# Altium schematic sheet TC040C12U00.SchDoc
size A2
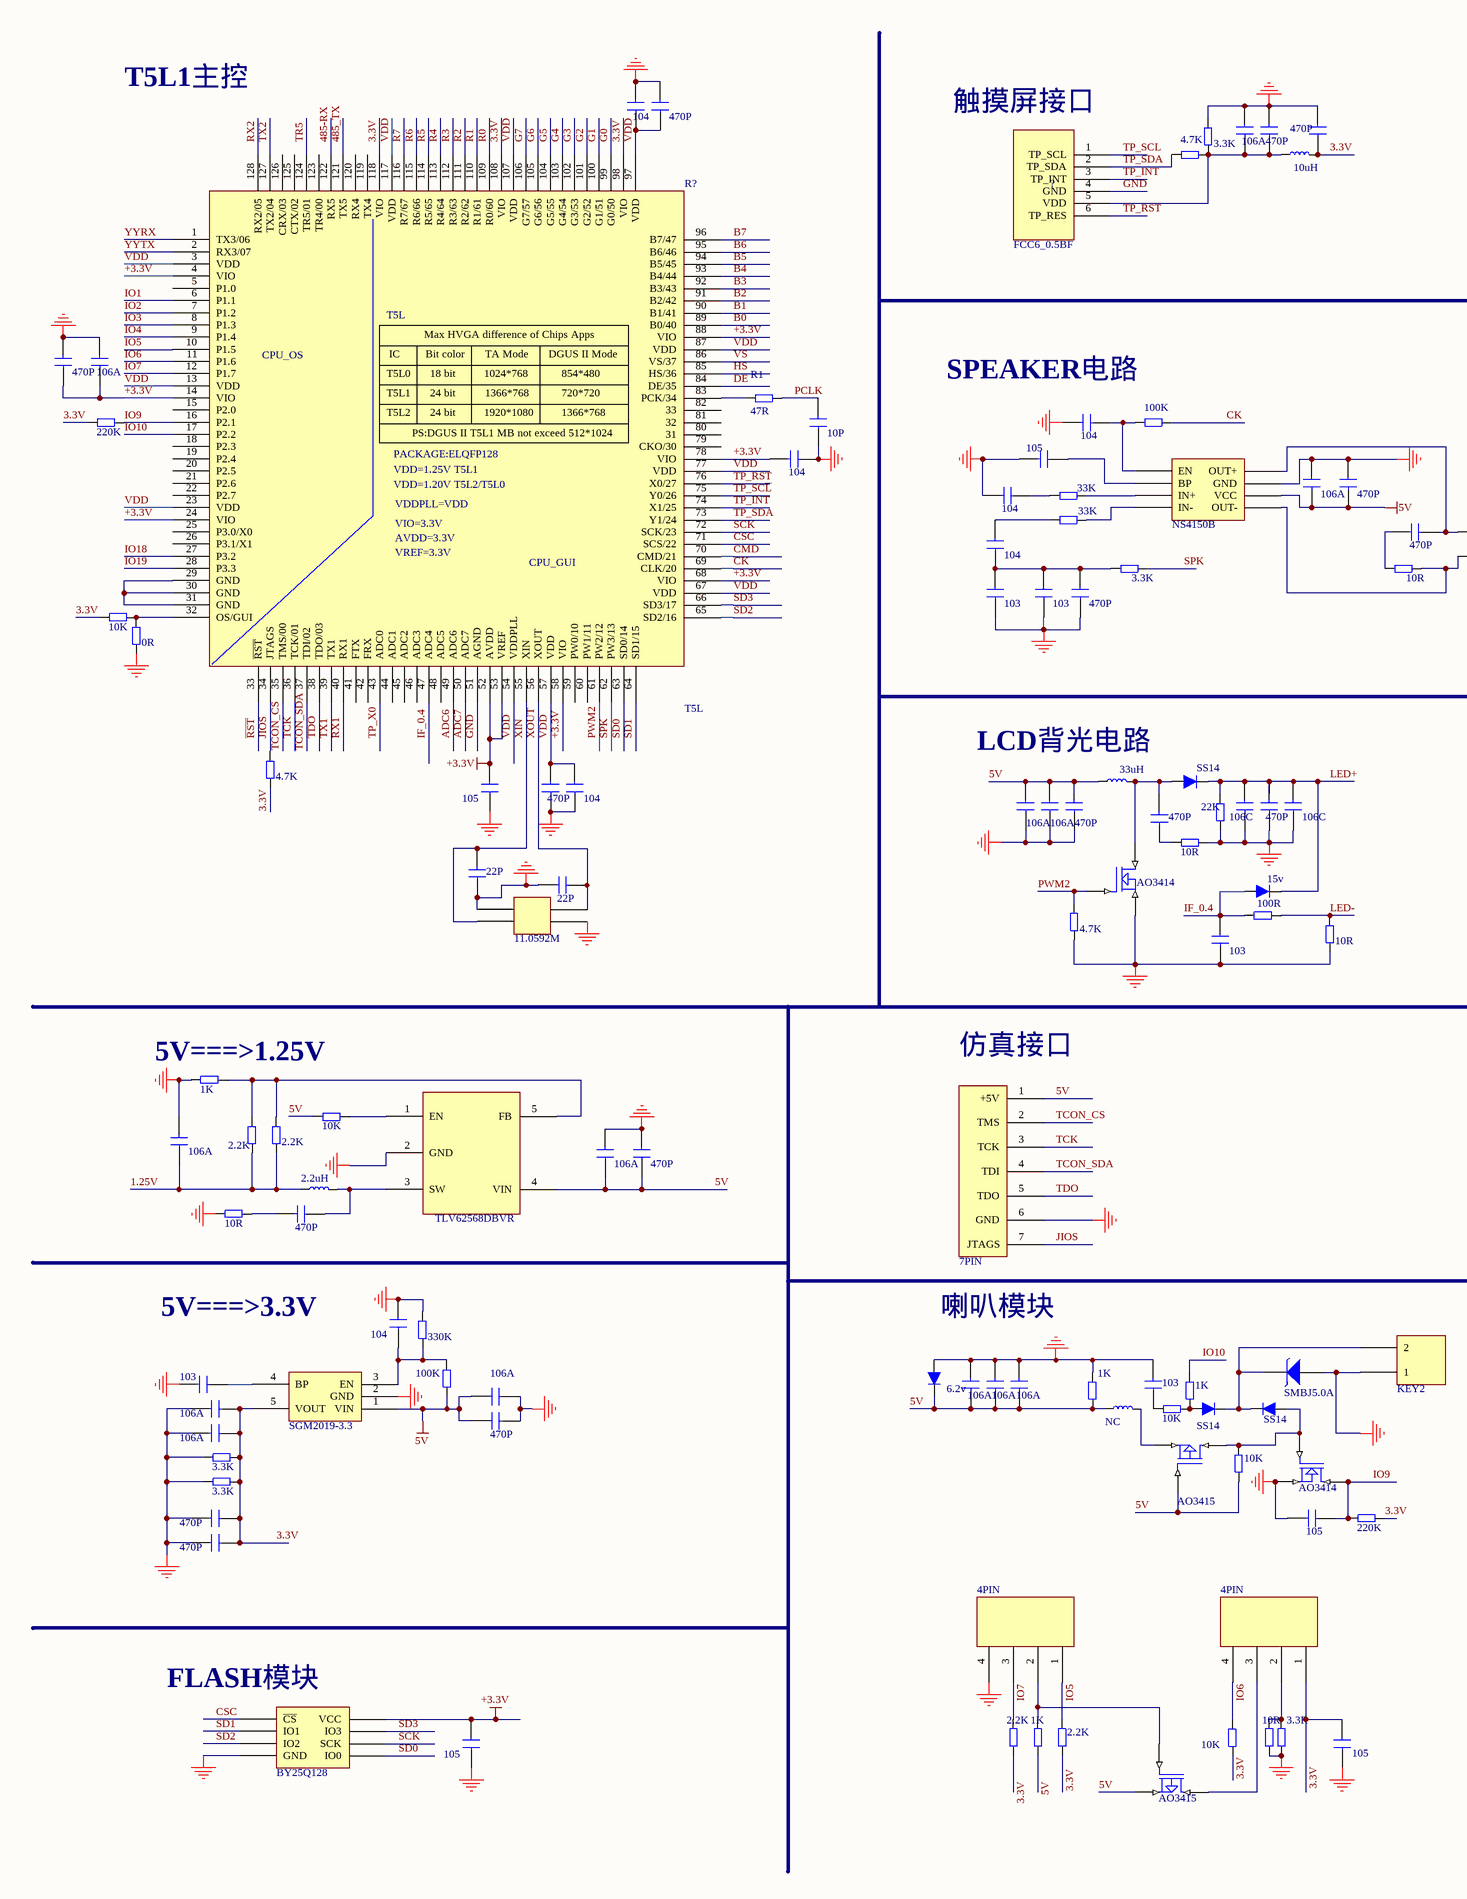
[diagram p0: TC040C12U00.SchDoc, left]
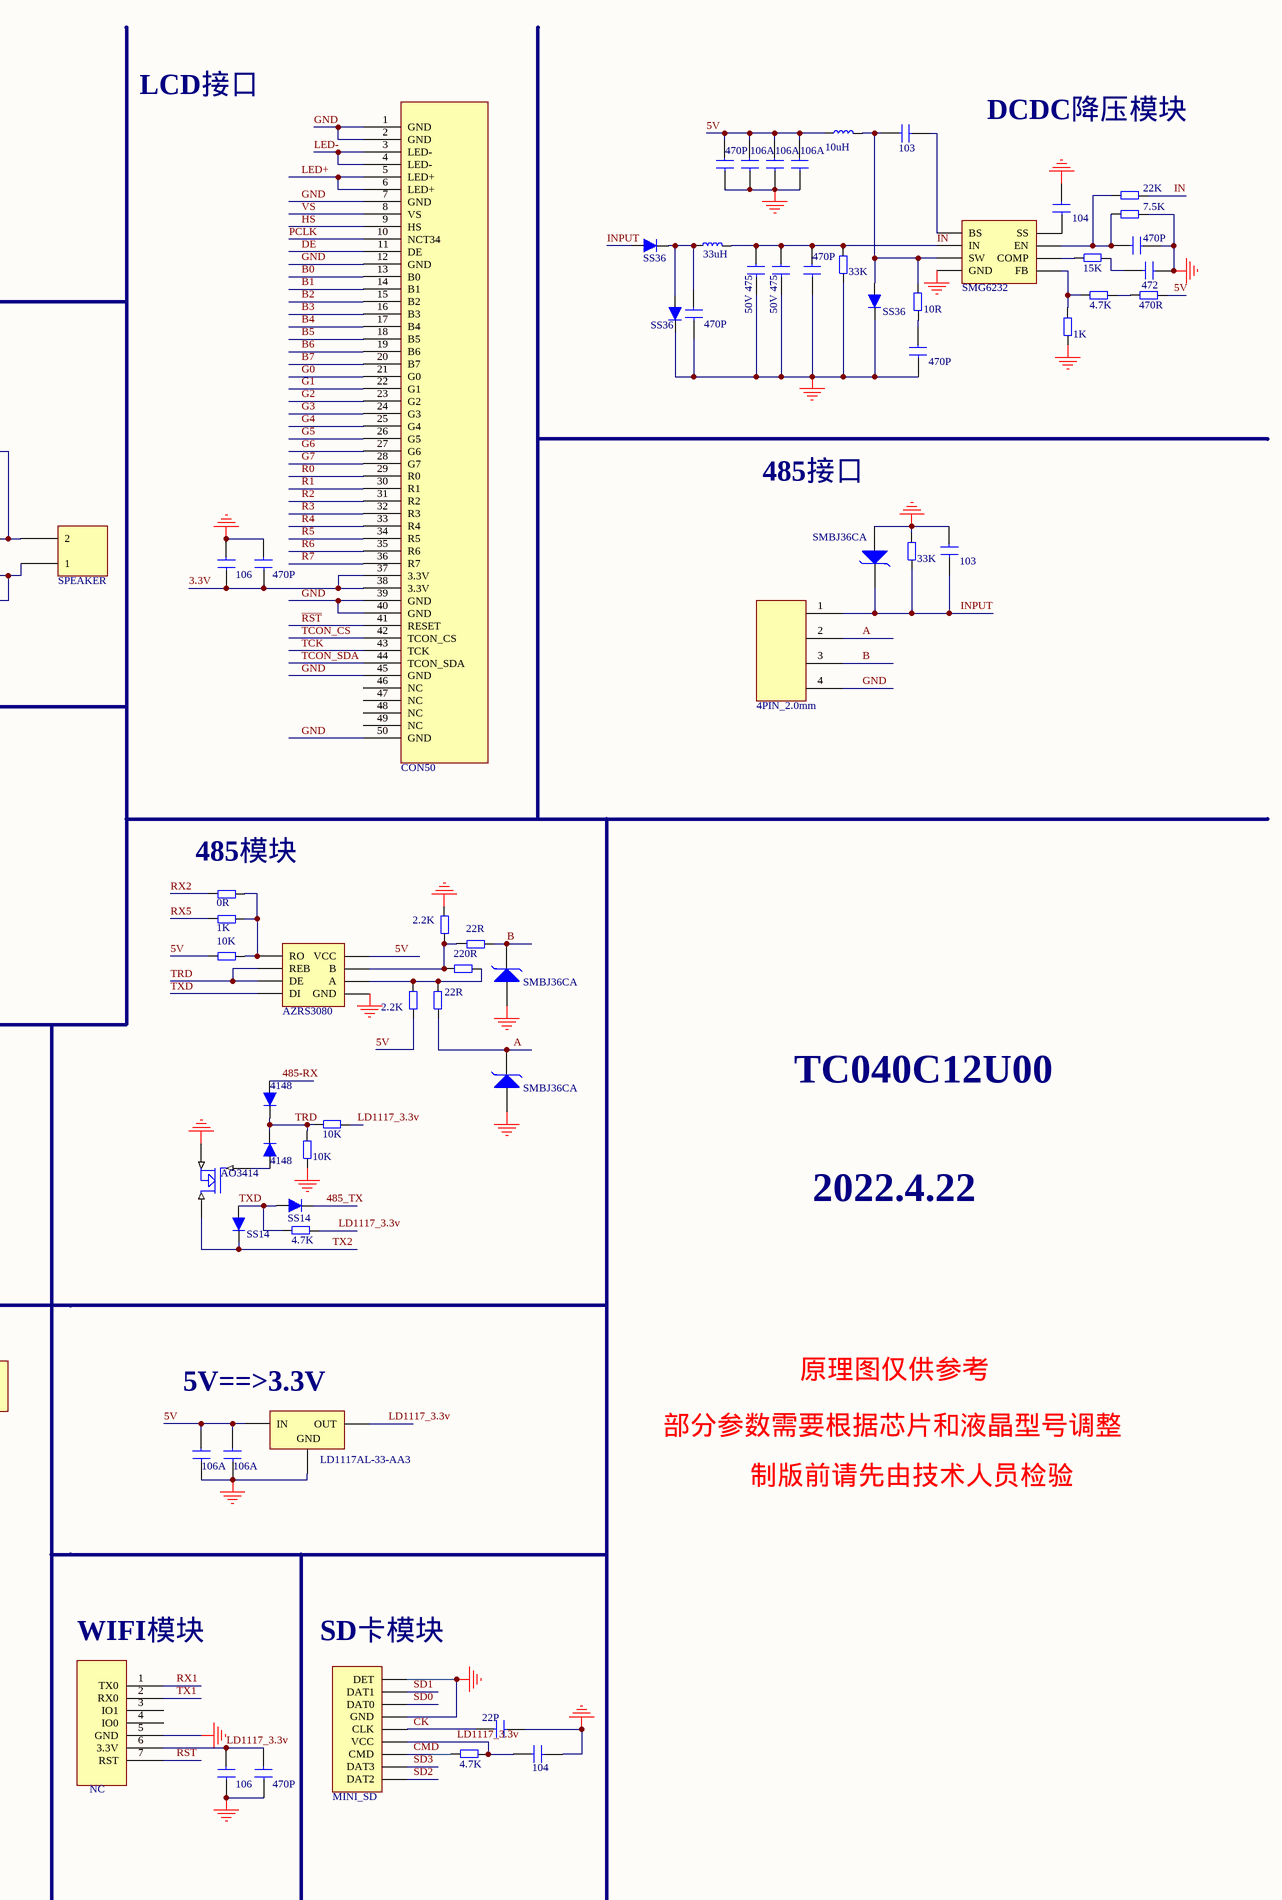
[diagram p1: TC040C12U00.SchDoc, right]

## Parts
(Parts that share a designator on the sheet are numbered #1, #2 ... from top to bottom, then left to right.)
*  SMG6232
?#1  10uH  [L0606]
?#2  103  [C0603]
?#3  106A  [C0603]
?#4  470P  [C0603]
?#5  470P  [C0603]
?#6  4.7K  [R0603]
?#7  3.3K  [R0603]
?#8  10uH  [L0606]
?#9  470P  [C0603]
?#10  106A  [C0603]
?#11  106A  [C0603]
?#12  106A  [C0603]
?#13  22K  [R0603]
?#14  CON50
?#15  7.5K  [R0603]
?#16  104  [C0603]
?#17  FCC6_0.5BF
?#18  SS36  [4148s]
?#19  33uH  [L0606]
?#20  470P  [C0603]
?#21  50V 475  [C0603]
?#22  50V 475  [C0603]
?#23  470P  [C0603]
?#24  15K  [R0603]
?#25  472  [C0603]
?#26  33K  [R0603]
?#27  4.7K  [R0603]
?#28  470R  [R0603]
?#29  470P  [C0603]
?#30  SS36  [4148s]
?#31  SS36  [4148s]
?#32  10R  [R0603]
?#33  470P  [C0603]
?#34  1K  [R0603]
?#35  220K  [R0603]
?#36  104  [C0603]
?#37  100K  [R0402]
?#38  105  [C0603]
?#39  106A  [C0603]
?#40  470P  [C0603]
?#41  104  [C0603]
?#42  33K  [R0402]
?#43  33K  [R0402]
?#44  NS4150B  [MSOP8]
?#45  470P  [C0603]
?#46  103  [C0603]
?#47  SPEAKER
?#48  104  [C0603]
?#49  SMBJ36CA  [5822]
?#50  33K  [R0603]
?#51  3.3K  [R0402]
?#52  10R  [R0603]
?#53  106  [C0603]
?#54  470P  [C0603]
?#55  103  [C0603]
?#56  103  [C0603]
?#57  470P  [C0603]
?#58  10K  [R0603]
?#59  0R  [R0603]
?#60  4PIN_2.0mm
?#61  33uH  [L0606]
?#62  SS14  [4148s]
?#63  105  [C0603]
?#64  470P  [C0603]
?#65  104  [C0603]
?#66  106A  [C0603]
?#67  106A  [C0603]
?#68  470P  [C0603]
?#69  106C  [C0603]
?#70  470P  [C0603]
?#71  106C  [C0603]
?#72  470P  [C0603]
?#73  22K  [R0603]
?#74  10R  [R0603]
?#75  AO3414  [SOT23-3]
?#76  0R  [R0603]
?#77  22P  [C0603]
?#78  22P  [C0603]
?#79  15v  [SOD323]
?#80  2.2K  [R0603]
?#81  1K  [R0603]
?#82  100R  [R0603]
?#83  103  [C0603]
?#84  22R  [R0603]
?#85  4.7K  [R0402]
?#86  10K  [R0603]
?#87  10R  [R0603]
?#88  220R  [R0603]
?#89  SMBJ36CA  [5822]
?#90  11.0592M
?#91  AZRS3080  [SO-8]
?#92  2.2K  [R0603]
?#93  22R  [R0603]
?#94  SMBJ36CA  [5822]
?#95  1K  [R0603]
?#96  4148  [4148s]
?#97  10K  [R0603]
?#98  10K  [R0603]
?#99  4148  [4148s]
?#100  10K  [R0603]
?#101  106A  [C0603]
?#102  2.2K  [R0603]
?#103  2.2K  [R0603]
?#104  TLV62568DBVR
?#105  106A  [C0603]
?#106  470P  [C0603]
?#107  AO3414  [SOT23-3]
?#108  SS14  [4148s]
?#109  2.2uH  [L0606]
?#110  7PIN
?#111  SS14  [4148s]
?#112  4.7K  [R0603]
?#113  10R  [R0603]
?#114  470P  [C0603]
?#115  104  [C0603]
?#116  330K  [R0402]
?#117  6.2v  [SOD323]
?#118  KEY2
?#119  SMBJ5.0A  [5822]
?#120  103  [C0603]
?#121  100K  [R0402]
?#122  106A  [C0603]
?#123  106A  [C0603]
?#124  106A  [C0603]
?#125  106A  [C0603]
?#126  103  [C0603]
?#127  106A  [C0603]
?#128  1K  [R0603]
?#129  NC  [L0606]
?#130  10K  [R0603]
?#131  1K  [R0603]
?#132  SS14  [4148s]
?#133  SS14  [4148s]
?#134  106A  [C0603]
?#135  106A  [C0603]
?#136  SGM2019-3.3  [SOT23-5]
?#137  470P  [C0603]
?#138  106A  [C0603]
?#139  3.3K  [R0603]
?#140  AO3414  [SOT23-3]
?#141  AO3415
?#142  3.3K  [R0603]
?#143  10K  [R0603]
?#144  470P  [C0603]
?#145  105  [C0603]
?#146  220K  [R0603]
?#147  470P  [C0603]
?#148  4PIN
?#149  4PIN
?#150  22P  [C0603]
?#151  NC
?#152  2.2K  [R0603]
?#153  1K  [R0603]
?#154  2.2K  [R0603]
?#155  10R  [R0603]
?#156  3.3R  [R0603]
?#157  4.7K  [R0402]
?#158  104  [C0603]
?#159  106  [C0603]
?#160  470P  [C0603]
?#161  105  [C0603]
?#162  10K  [R0603]
?#163  105  [C0603]
?#164  MINI_SD  [MINI_SD]
?#165  AO3415
C1  470P  [C0603]
C2  106A  [C0603]
C3  104  [C0603]
C4  470P  [C0603]
C5  10P  [C0603]
C6  104  [C0603]
R1  47R  [R0603]
R2  4.7K  [R0603]
R?  T5L
U1  BY25Q128  [SO-8L]
VD?  LD1117AL-33-AA3  [SOT-223]

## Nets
5V: ?#1.1 ?#9.1 ?#10.1 ?#11.1 ?#12.1 ?#28.1 ?#39.2 ?#40.2 ?#44.VCC ?#61.1 ?#66.2 ?#67.2 ?#68.2 ?#86.1 ?#91.VCC ?#92.1 ?#98.1 ?#104.4(VIN) ?#105.1 ?#106.1 ?#110.1(+5V) ?#117.2(K) ?#121.1 ?#122.2 ?#123.1 ?#124.1 ?#125.1 ?#128.1 ?#129.1 ?#134.1 ?#135.1 ?#136.1(VIN) ?#137.2 ?#141.1(G) ?#143.1 ?#153.2 ?#165.3(S) VD?.3(IN)
+3.3V: ?#63.2 ?#161.2 C1.1 C2.1 C6.1 R?.4(VIO) R?.14(VIO) R?.24(VIO) R?.52(AVDD) R?.53(VREF) R?.58(VIO) R?.68(VIO) R?.78(VIO) R?.88(VIO) U1.VCC
GND: *.4(GND) ?#3.2 ?#4.2 ?#5.2 ?#7.2 ?#9.2 ?#10.2 ?#11.2 ?#12.2 ?#14.1(GND) ?#14.2(GND) ?#14.7(GND) ?#14.12(GND) ?#14.39(GND) ?#14.40(GND) ?#14.45(GND) ?#14.50(GND) ?#15.1 ?#16.2 ?#17.4(GND) ?#20.2 ?#21.2 ?#22.2 ?#23.2 ?#25.2 ?#26.1 ?#29.2 ?#30.2(K) ?#31.2(K) ?#33.2 ?#34.1 ?#36.1 ?#38.1 ?#39.1 ?#40.1 ?#41.1 ?#44.GND ?#46.1 ?#49.1(A) ?#50.2 ?#53.2 ?#54.2 ?#55.1 ?#56.1 ?#57.1 ?#59.1 ?#60.4 ?#63.1 ?#64.1 ?#65.1 ?#66.1 ?#67.1 ?#68.1 ?#69.1 ?#70.1 ?#71.1 ?#73.1 ?#74.2 ?#75.3(S) ?#77.1 ?#78.2 ?#80.1 ?#83.2 ?#85.1 ?#87.1 ?#89.1(A) ?#90.?1 ?#90.?4 ?#91.GND ?#94.1(A) ?#95.2 ?#100.1 ?#101.2 ?#104.2(GND) ?#105.2 ?#106.2 ?#107.3(S) ?#110.6(GND) ?#113.2 ?#115.1 ?#116.2 ?#117.1(A) ?#118.?1(1) ?#119.1(A) ?#120.2 ?#122.1 ?#123.2 ?#124.2 ?#125.2 ?#126.2 ?#127.2 ?#128.2 ?#134.2 ?#135.2 ?#136.2(GND) ?#137.1 ?#138.2 ?#139.2 ?#140.3(S) ?#142.2 ?#144.2 ?#145.1 ?#147.2 ?#148.4 ?#150.1 ?#151.5(GND) ?#155.2 ?#156.2 ?#158.1 ?#159.1 ?#160.1 ?#161.1 ?#163.1 ?#164.DET ?#164.GND C1.2 C2.2 C3.2 C4.2 C5.1 C6.2 R?.51(AGND) U1.GND VD?.1(GND)
1.25V: ?#101.1 ?#102.1 ?#103.1 ?#109.1
3.3V: ?#5.1 ?#8.2 ?#14.37(3.3V) ?#14.38(3.3V) ?#35.1 ?#53.1 ?#54.1 ?#58.2 ?#127.1 ?#136.5(VOUT) ?#138.1 ?#139.1 ?#142.1 ?#144.1 ?#146.1 ?#147.1 ?#149.1 ?#152.2 ?#154.2 ?#162.1 ?#163.2 R2.1 R?.98(VIO) R?.108(VIO) R?.118(VIO)
485-RX: ?#96.1(A) R?.122(RX5)
485_TX: ?#108.2(K) R?.121(TX5)
A: ?#60.2 ?#93.1 ?#94.2(K)
ADC6: R?.49(ADC6)
ADC7: R?.50(ADC7)
B: ?#60.3 ?#84.2 ?#89.2(K)
B0: ?#14.13(B0) R?.89(B0/40)
B1: ?#14.14(B1) R?.90(B1/41)
B2: ?#14.15(B2) R?.91(B2/42)
B3: ?#14.16(B3) R?.92(B3/43)
B4: ?#14.17(B4) R?.93(B4/44)
B5: ?#14.18(B5) R?.94(B5/45)
B6: ?#14.19(B6) R?.95(B6/46)
B7: ?#14.20(B7) R?.96(B7/47)
CK: ?#37.2 ?#150.2 ?#164.CLK R?.69(CLK/20)
CMD: ?#157.2 ?#164.CMD R?.70(CMD/21)
CSC: R?.71(SCS/22) U1.CS(~{CS})
DE: ?#14.11(DE) R?.84(DE/35)
G0: ?#14.21(G0) R?.99(G0/50)
G1: ?#14.22(G1) R?.100(G1/51)
G2: ?#14.23(G2) R?.101(G2/52)
G3: ?#14.24(G3) R?.102(G3/53)
G4: ?#14.25(G4) R?.103(G4/54)
G5: ?#14.26(G5) R?.104(G5/55)
G6: ?#14.27(G6) R?.105(G6/56)
G7: ?#14.28(G7) R?.106(G7/57)
HS: ?#14.9(HS) R?.85(HS/36)
IF_0.4: ?#79.1(A) ?#82.2 ?#83.1 R?.47(ADC4)
IN: *.2(IN) ?#13.1 ?#19.2 ?#21.1 ?#22.1 ?#23.1 ?#26.2
INPUT: ?#18.1(A) ?#46.2 ?#49.2(K) ?#50.1 ?#60.1
IO1: R?.6(P1.1)
IO2: R?.7(P1.2)
IO3: R?.8(P1.3)
IO4: R?.9(P1.4)
IO5: ?#148.1 ?#154.1 R?.10(P1.5)
IO6: ?#149.4 ?#162.2 R?.11(P1.6)
IO7: ?#148.3 ?#152.1 R?.12(P1.7)
IO9: ?#35.2 ?#140.2(D) ?#145.2 ?#146.2 R?.16(P2.1)
IO10: ?#131.2 R?.17(P2.2)
IO18: R?.27(P3.2)
IO19: R?.28(P3.3)
JIOS: ?#110.7(JTAGS) R2.2 R?.34(JTAGS)
LD1117_3.3v: ?#97.1 ?#112.1 ?#151.6(3.3V) ?#157.1 ?#158.2 ?#159.2 ?#160.2 ?#164.VCC VD?.2(OUT)
LED+: ?#14.5(LED+) ?#14.6(LED+) ?#62.2(K) ?#69.2 ?#70.2 ?#71.2 ?#73.2 ?#79.2(K)
LED-: ?#14.3(LED-) ?#14.4(LED-) ?#82.1 ?#87.2
PCLK: ?#14.10(NCT34) C5.2 R1.2
PWM2: ?#75.1(G) ?#85.2 R?.61(PW2/12)
R0: ?#14.29(R0) R?.109(R0/60)
R1: ?#14.30(R1) R?.110(R1/61)
R2: ?#14.31(R2) R?.111(R2/62)
R3: ?#14.32(R3) R?.112(R3/63)
R4: ?#14.33(R4) R?.113(R4/64)
R5: ?#14.34(R5) R?.114(R5/65)
R6: ?#14.35(R6) R?.115(R6/66)
R7: ?#14.36(R7) R?.116(R7/67)
~{RST}: ?#14.41(RESET) ?#151.7(RST) R?.33(~{RST})
RX1: ?#151.1(TX0) R?.40(RX1)
RX2: ?#76.1 R?.128(RX2/05)
RX5: ?#81.1
SCK: R?.72(SCK/23) U1.CLK(SCK)
SD0: ?#164.DAT0 R?.63(SD0/14) U1.IO0
SD1: ?#164.DAT1 R?.64(SD1/15) U1.IO1
SD2: ?#164.DAT2 R?.65(SD2/16) U1.IO2
SD3: ?#164.DAT3 R?.66(SD3/17) U1.IO3
SPK: ?#51.2 R?.62(PW3/13)
TCK: ?#14.43(TCK) ?#110.3(TCK) R?.36(TCK/01)
TCON_CS: ?#14.42(TCON_CS) ?#110.2(TMS) R?.35(TMS/00)
TCON_SDA: ?#14.44(TCON_SDA) ?#110.4(TDI) R?.37(TDI/02)
TDO: ?#110.5(TDO) R?.38(TDO/03)
TP_INT: ?#17.3(TP_INT) R?.74(X1/25)
TP_RST: ?#17.6(TP_RES) R?.76(X0/27)
TP_SCL: ?#17.1(TP_SCL)
TP_SC~{L}: R?.75(Y0/26)
TP_SDA: ?#6.1 ?#17.2(TP_SDA) R?.73(Y1/24)
TP_X0: R?.43(ADC0)
TR5: R?.124(TR5/01)
TRD: ?#91.2(REB) ?#91.3(DE) ?#96.2(K) ?#97.2 ?#99.2(K) ?#100.2
TX1: ?#151.2(RX0) R?.39(TX1)
TX2: ?#107.2(D) ?#111.2(K) R?.127(TX2/04)
TXD: ?#91.DI ?#108.1(A) ?#111.1(A) ?#112.2
VDD: ?#64.2 ?#65.2 C3.1 C4.1 R?.3(VDD) R?.13(VDD) R?.23(VDD) R?.54(VDDPLL) R?.57(VDD) R?.67(VDD) R?.77(VDD) R?.87(VDD) R?.97(VDD) R?.107(VDD) R?.117(VDD)
VS: ?#14.8(VS) R?.86(VS/37)
XIN: ?#77.2 ?#90.?2 R?.55(XIN)
XOUT: ?#78.1 ?#90.?3 R?.56(XOUT)
YYRX: R?.1(TX3/06)
YYTX: R?.2(RX3/07)
Net*_1: *.1(BS) ?#2.1
Net*_3: *.3(SW) ?#1.2 ?#2.2 ?#30.1(A) ?#32.2
Net*_5: *.5(FB) ?#27.2 ?#34.2
Net*_6: *.6(COMP) ?#24.2
Net*_7: *.7(EN) ?#13.2 ?#15.2 ?#20.1
Net*_8: *.8(SS) ?#16.1
Net?#3_1: ?#3.1 ?#4.1 ?#6.2 ?#7.1 ?#8.1 ?#17.5(VDD)
Net?#18_2: ?#18.2(K) ?#19.1 ?#29.1 ?#31.1(A)
Net?#24_1: ?#24.1 ?#25.1
Net?#27_1: ?#27.1 ?#28.2
Net?#32_1: ?#32.1 ?#33.1
Net?#36_2: ?#36.2 ?#37.1 ?#44.CTRL(EN)
Net?#38_2: ?#38.2 ?#44.Bypass(BP)
Net?#41_2: ?#41.2 ?#42.1
Net?#42_2: ?#42.2 ?#44.INP(IN+)
Net?#43_1: ?#43.1 ?#48.2
Net?#43_2: ?#43.2 ?#44.INN(IN-)
Net?#44_VON: ?#44.VON(OUT-) ?#47.?1(1) ?#52.2
Net?#44_VOP: ?#44.VOP(OUT+) ?#45.1 ?#47.?2(2)
Net?#45_2: ?#45.2 ?#52.1
Net?#48_1: ?#48.1 ?#51.1 ?#55.2 ?#56.2 ?#57.2
Net?#58_1: ?#58.1 ?#59.2 R?.32(OS/GUI)
Net?#61_2: ?#61.2 ?#62.1(A) ?#72.2 ?#75.2(D)
Net?#72_1: ?#72.1 ?#74.1
Net?#76_2: ?#76.2 ?#81.2 ?#86.2 ?#91.RE(RO)
Net?#80_2: ?#80.2 ?#84.1 ?#88.1 ?#91.B
Net?#88_2: ?#88.2 ?#91.A ?#92.2 ?#93.2
Net?#95_1: ?#95.1 ?#102.2 ?#103.2 ?#104.5(FB)
Net?#98_2: ?#98.2 ?#104.1(EN)
Net?#99_1: ?#99.1(A) ?#107.1(G)
Net?#104_3: ?#104.3(SW) ?#109.2 ?#114.2
Net?#113_1: ?#113.1 ?#114.1
Net?#115_2: ?#115.2 ?#116.1 ?#121.2 ?#136.3(EN)
Net?#118_?2: ?#118.?2(2) ?#119.2(K) ?#132.2(K) ?#133.2(K)
Net?#120_1: ?#120.1 ?#136.4(BP)
Net?#126_1: ?#126.1 ?#130.1
Net?#129_2: ?#129.2 ?#141.3(S)
Net?#130_2: ?#130.2 ?#131.1 ?#132.1(A)
Net?#133_1: ?#133.1(A) ?#140.1(G) ?#141.2(D) ?#143.2
Net?#148_2: ?#148.2 ?#153.1 ?#165.1(G)
Net?#149_2: ?#149.2 ?#155.1 ?#156.1
Net?#149_3: ?#149.3 ?#165.2(D)
NetR1_1: R1.1 R?.83(PCK/34)
NetR?_29: R?.29(GND) R?.30(GND) R?.31(GND)

Not connected (* = marked no-connect by the designer): ?#14 46(NC) 47(NC) 48(NC) 49(NC); ?#151 3(IO1) 4(IO0); R? 5(P1.0) 15(P2.0) 18(P2.3) 19(P2.4) 20(P2.5) 21(P2.6) 22(P2.7) 25(P3.0/X0) 26(P3.1/X1) 41(FTX) 42(FRX) 44(ADC1) 45(ADC2) 46(ADC3) 48(ADC5) 59(PW0/10) 60(PW1/11) 79(CKO/30) 80(31) 81(32) 82(33) 119(TX4) 120(RX4) 123(TR4/00) 125(CTX/02) 126(CRX/03)

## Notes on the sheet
- T5L1主控
- LCD接口
- 触摸屏接口
- DCDC降压模块
- (near ?#36) SPEAKER电路
- 485接口
- (near ?#61) LCD背光电路
- (near ?#76) 485模块
- (near ?#95) 5V===>1.25V
- (near ?#110) 仿真接口
- 5V===>3.3V
- (near ?#110) 喇叭模块
- (near VD?) 5V==>3.3V
- (near ?#151) WIFI模块
- (near ?#164) SD卡模块
- (near U1) FLASH模块
- Labels drawn without touching a wire or pin: 2022.4.22, TC040C12U00, 制版前请先由技术人员检验, 原理图仅供参考, 部分参数需要根据芯片和液晶型号调整

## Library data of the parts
?#1 ?#8 ?#19 ?#61 ?#109 ?#129 = L
?#2-?#5 ?#9-?#12 ?#16 ?#20-?#23 ?#25 ?#29 ?#33 ?#36 ?#38-?#41 ?#45 ?#46 ?#48 ?#53-?#57 ?#63-?#72 ?#77 ?#78 ?#83 ?#101 ?#105 ?#106 ?#114 ?#115 ?#120 ?#122-?#127 ?#134 ?#135 ?#137 ?#138 ?#144 ?#145 ?#147 ?#150 ?#158-?#161 ?#163 C1-C6 = C
?#6 ?#7 ?#13 ?#15 ?#24 ?#26-?#28 ?#32 ?#34 ?#35 ?#37 ?#42 ?#43 ?#50-?#52 ?#58 ?#59 ?#73 ?#74 ?#76 ?#80-?#82 ?#84-?#88 ?#92 ?#93 ?#95 ?#97 ?#98 ?#100 ?#102 ?#103 ?#112 ?#113 ?#116 ?#121 ?#128 ?#130 ?#131 ?#139 ?#142 ?#143 ?#146 ?#152-?#157 ?#162 R1 R2 = R: *
?#14 = FCC50_0.5
?#18 ?#30 ?#31 ?#62 ?#96 ?#99 ?#108 ?#111 ?#132 ?#133 = D
?#47 ?#118 = 2PIN
?#49 ?#89 ?#94 ?#119 = SMBJ15A
?#60 = 4PIN
?#75 ?#107 ?#140 = MOSFET N
?#79 ?#117 = DIODE ZENER
?#90 = 32768晶振
?#141 ?#165 = MOSFET P
?#151 = WIFI模块
?#164 = SD1
VD? = AMS1117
